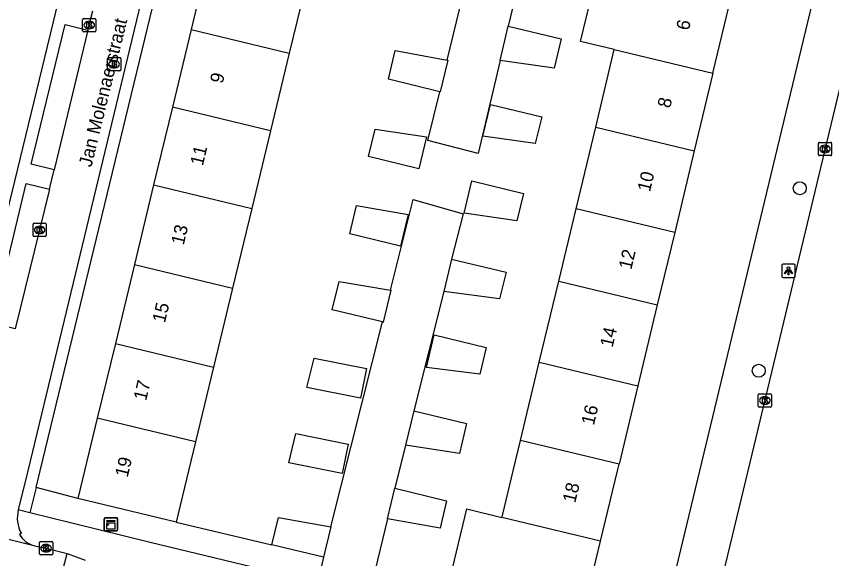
# Model space of a CAD drawing. Extents: x 162812 to 163818, y 381639 to 382470.
# Drawn here: x 163142.2 to 163203.7, y 382243.4 to 382284.3 of the extents above; entities that cross this region are included whole.
import ezdxf

# ---------------------------------------------------------------- set-up
doc = ezdxf.new("R2010")
doc.units = 0
for name, color, linetype in [('IMGEO_Boom', 7, 'Continuous'), ('IMGEO_Brandkraan', 7, 'Continuous'), ('IMGEO_Groenvoorziening', 7, 'Continuous'), ('IMGEO_Kast', 7, 'Continuous'), ('IMGEO_Kolk', 7, 'Continuous'), ('IMGEO_Lichtpunt', 7, 'Continuous'), ('IMGEO_Openbare_ruimte_label', 7, 'Continuous'), ('IMGEO_Pand', 7, 'Continuous'), ('IMGEO_Pand_nummerreeks', 7, 'Continuous'), ('IMGEO_Rijbaan_lokaal_open', 7, 'Continuous'), ('IMGEO_Voetpad_open', 7, 'Continuous')]:
    doc.layers.add(name, color=color, linetype=linetype)

msp = doc.modelspace()

# ---------------------------------------------------------------- linework, layer by layer
at = {"layer": 'IMGEO_Boom'}
for centre in [(163201.327, 382271.309), (163198.228, 382257.543)]:
    msp.add_circle(centre, 0.489, dxfattribs=at)
at = {"layer": 'IMGEO_Brandkraan'}
for p, q in [((163149.116, 382280.236), (163149.116, 382281.088)), ((163149.191, 382281.162), (163150.043, 382281.162)), ((163149.604, 382280.942), (163149.629, 382280.942)), ((163150.117, 382281.088), (163150.117, 382280.236)), ((163150.043, 382280.162), (163149.191, 382280.162)), ((163149.627, 382280.382), (163149.602, 382280.382))]:
    msp.add_line(p, q, dxfattribs=at)
for points in [[(163149.116, 382280.236), (163149.116, 382281.088)], [(163149.191, 382281.162), (163150.043, 382281.162)], [(163149.464, 382280.862), (163149.464, 382280.462), (163149.677, 382280.462)], [(163149.695, 382280.862), (163149.464, 382280.862)], [(163149.643, 382280.781), (163149.589, 382280.781), (163149.589, 382280.705)], [(163150.117, 382281.088), (163150.117, 382280.236)], [(163150.043, 382280.162), (163149.191, 382280.162)], [(163149.589, 382280.705), (163149.642, 382280.705)], [(163149.651, 382280.629), (163149.589, 382280.629), (163149.589, 382280.548)], [(163149.589, 382280.548), (163149.651, 382280.548)]]:
    msp.add_lwpolyline(points, dxfattribs=at)
for centre, radius, start, end in [((163149.193, 382281.086), 0.0765, 91.55205, 178.44795), ((163149.193, 382281.086), 0.0765, 91.55205, 178.44795), ((163149.644, 382280.743), 0.0379, 267.82845, 90.93552), ((163149.699, 382280.717), 0.145, 59.4692, 91.53667), ((163149.724, 382280.764), 0.0922, 285.51372, 58.15012), ((163150.041, 382281.086), 0.0765, 1.55205, 88.44795), ((163150.041, 382281.086), 0.0765, 1.55205, 88.44795), ((163149.193, 382280.238), 0.0765, 181.55205, 268.44795), ((163149.193, 382280.238), 0.0765, 181.55205, 268.44795), ((163149.652, 382280.588), 0.0404, 269.87594, 90.50774), ((163149.683, 382280.713), 0.251, 268.66757, 293.53466), ((163149.729, 382280.572), 0.105, 301.31148, 78.98903), ((163150.041, 382280.238), 0.0765, 271.55205, 358.44795), ((163150.041, 382280.238), 0.0765, 271.55205, 358.44795)]:
    msp.add_arc(centre, radius, start, end, dxfattribs=at)
for centre, major_axis, ratio, start_param, end_param in [((163149.603, 382280.662), (-0.387, 0.002), 0.722429, 4.712389, 7.853982), ((163149.628, 382280.662), (-0.39, 0.002), 0.717154, 1.570796, 4.712389)]:
    msp.add_ellipse(centre, major_axis=major_axis, ratio=ratio, start_param=start_param, end_param=end_param, dxfattribs=at)
at = {"layer": 'IMGEO_Groenvoorziening'}
for points in [[(163146.893, 382247.921), (163143.732, 382248.734)], [(163154.299, 382246.14), (163161.513, 382244.425)]]:
    msp.add_lwpolyline(points, dxfattribs=at)
at = {"layer": 'IMGEO_Kast'}
for p, q in [((163148.882, 382245.539), (163148.882, 382246.38)), ((163148.882, 382246.38), (163148.882, 382245.539)), ((163148.957, 382246.464), (163149.798, 382246.464)), ((163149.798, 382246.464), (163148.957, 382246.464)), ((163149.882, 382246.389), (163149.882, 382245.548)), ((163149.882, 382245.548), (163149.882, 382246.389)), ((163149.807, 382245.464), (163148.966, 382245.464)), ((163148.966, 382245.464), (163149.807, 382245.464))]:
    msp.add_line(p, q, dxfattribs=at)
for points in [[(163149.077, 382246.254), (163149.677, 382246.254), (163149.677, 382246.169), (163149.077, 382246.169), (163149.077, 382246.254)], [(163149.077, 382246.079), (163149.677, 382246.079), (163149.677, 382245.59), (163149.077, 382245.59), (163149.077, 382246.079)]]:
    msp.add_lwpolyline(points, dxfattribs=at)
msp.add_circle((163149.161, 382245.928), 0.0377, dxfattribs=at)
for centre, start, end in [((163148.96, 382246.386), 92.4484, 184.28452), ((163148.96, 382246.386), 92.4484, 184.28452), ((163149.804, 382246.386), 2.4484, 94.28452), ((163149.804, 382246.386), 2.4484, 94.28452), ((163148.96, 382245.542), 182.4484, 274.28452), ((163148.96, 382245.542), 182.4484, 274.28452), ((163149.804, 382245.542), 272.4484, 4.28452), ((163149.804, 382245.542), 272.4484, 4.28452)]:
    msp.add_arc(centre, 0.0779, start, end, dxfattribs=at)
at = {"layer": 'IMGEO_Kolk'}
for p, q in [((163147.25, 382283.191), (163147.25, 382284.043)), ((163147.325, 382284.117), (163148.177, 382284.117)), ((163147.738, 382283.897), (163147.763, 382283.897)), ((163148.251, 382284.043), (163148.251, 382283.191)), ((163147.761, 382283.337), (163147.736, 382283.337)), ((163148.177, 382283.117), (163147.325, 382283.117)), ((163202.728, 382273.845), (163202.728, 382274.697)), ((163202.803, 382274.771), (163203.655, 382274.771)), ((163203.729, 382274.697), (163203.729, 382273.845)), ((163203.239, 382273.991), (163203.214, 382273.991)), ((163203.216, 382274.551), (163203.241, 382274.551)), ((163203.655, 382273.771), (163202.803, 382273.771)), ((163143.506, 382267.741), (163143.506, 382268.593)), ((163143.581, 382268.667), (163144.433, 382268.667)), ((163143.994, 382268.447), (163144.019, 382268.447)), ((163144.507, 382268.593), (163144.507, 382267.741)), ((163144.017, 382267.887), (163143.992, 382267.887)), ((163144.433, 382267.667), (163143.581, 382267.667)), ((163198.192, 382254.879), (163198.192, 382255.731)), ((163198.267, 382255.805), (163199.119, 382255.805)), ((163198.68, 382255.585), (163198.705, 382255.585)), ((163199.193, 382255.731), (163199.193, 382254.879)), ((163198.703, 382255.025), (163198.678, 382255.025)), ((163199.119, 382254.805), (163198.267, 382254.805)), ((163143.995, 382243.737), (163143.995, 382244.589)), ((163144.07, 382244.663), (163144.922, 382244.663)), ((163144.996, 382244.589), (163144.996, 382243.737)), ((163144.506, 382243.883), (163144.481, 382243.883)), ((163144.483, 382244.443), (163144.508, 382244.443)), ((163144.922, 382243.663), (163144.07, 382243.663))]:
    msp.add_line(p, q, dxfattribs=at)
for points in [[(163147.25, 382283.191), (163147.25, 382284.043)], [(163147.325, 382284.117), (163148.177, 382284.117)], [(163147.571, 382283.817), (163147.694, 382283.817), (163147.694, 382283.666), (163147.824, 382283.817), (163147.988, 382283.817), (163147.842, 382283.666), (163147.995, 382283.417), (163147.843, 382283.417), (163147.758, 382283.581), (163147.694, 382283.514), (163147.694, 382283.417), (163147.571, 382283.417), (163147.571, 382283.817)], [(163148.251, 382284.043), (163148.251, 382283.191)], [(163148.177, 382283.117), (163147.325, 382283.117)], [(163202.728, 382273.845), (163202.728, 382274.697)], [(163202.803, 382274.771), (163203.655, 382274.771)], [(163203.729, 382274.697), (163203.729, 382273.845)], [(163203.049, 382274.471), (163203.172, 382274.471), (163203.172, 382274.32), (163203.302, 382274.471), (163203.466, 382274.471), (163203.32, 382274.32), (163203.473, 382274.071), (163203.321, 382274.071), (163203.236, 382274.235), (163203.172, 382274.168), (163203.172, 382274.071), (163203.049, 382274.071), (163203.049, 382274.471)], [(163203.655, 382273.771), (163202.803, 382273.771)], [(163143.506, 382267.741), (163143.506, 382268.593)], [(163143.581, 382268.667), (163144.433, 382268.667)], [(163144.507, 382268.593), (163144.507, 382267.741)], [(163143.827, 382268.367), (163143.95, 382268.367), (163143.95, 382268.216), (163144.08, 382268.367), (163144.244, 382268.367), (163144.098, 382268.216), (163144.251, 382267.967), (163144.099, 382267.967), (163144.014, 382268.131), (163143.95, 382268.064), (163143.95, 382267.967), (163143.827, 382267.967), (163143.827, 382268.367)], [(163144.433, 382267.667), (163143.581, 382267.667)], [(163198.192, 382254.879), (163198.192, 382255.731)], [(163198.267, 382255.805), (163199.119, 382255.805)], [(163199.193, 382255.731), (163199.193, 382254.879)], [(163198.513, 382255.505), (163198.636, 382255.505), (163198.636, 382255.354), (163198.766, 382255.505), (163198.93, 382255.505), (163198.784, 382255.354), (163198.937, 382255.105), (163198.785, 382255.105), (163198.7, 382255.269), (163198.636, 382255.202), (163198.636, 382255.105), (163198.513, 382255.105), (163198.513, 382255.505)], [(163199.119, 382254.805), (163198.267, 382254.805)], [(163143.995, 382243.737), (163143.995, 382244.589)], [(163144.07, 382244.663), (163144.922, 382244.663)], [(163144.996, 382244.589), (163144.996, 382243.737)], [(163144.316, 382244.363), (163144.439, 382244.363), (163144.439, 382244.212), (163144.569, 382244.363), (163144.733, 382244.363), (163144.587, 382244.212), (163144.74, 382243.963), (163144.588, 382243.963), (163144.503, 382244.127), (163144.439, 382244.06), (163144.439, 382243.963), (163144.316, 382243.963), (163144.316, 382244.363)], [(163144.922, 382243.663), (163144.07, 382243.663)]]:
    msp.add_lwpolyline(points, dxfattribs=at)
for centre, start, end in [((163147.327, 382284.041), 91.55205, 178.44795), ((163147.327, 382284.041), 91.55205, 178.44795), ((163148.175, 382284.041), 1.55205, 88.44795), ((163148.175, 382284.041), 1.55205, 88.44795), ((163147.327, 382283.193), 181.55205, 268.44795), ((163147.327, 382283.193), 181.55205, 268.44795), ((163148.175, 382283.193), 271.55205, 358.44795), ((163148.175, 382283.193), 271.55205, 358.44795), ((163202.805, 382274.695), 91.55205, 178.44795), ((163202.805, 382274.695), 91.55205, 178.44795), ((163203.653, 382274.695), 1.55205, 88.44795), ((163203.653, 382274.695), 1.55205, 88.44795), ((163202.805, 382273.847), 181.55205, 268.44795), ((163202.805, 382273.847), 181.55205, 268.44795), ((163203.653, 382273.847), 271.55205, 358.44795), ((163203.653, 382273.847), 271.55205, 358.44795), ((163143.583, 382268.591), 91.55205, 178.44795), ((163143.583, 382268.591), 91.55205, 178.44795), ((163144.431, 382268.591), 1.55205, 88.44795), ((163144.431, 382268.591), 1.55205, 88.44795), ((163143.583, 382267.743), 181.55205, 268.44795), ((163143.583, 382267.743), 181.55205, 268.44795), ((163144.431, 382267.743), 271.55205, 358.44795), ((163144.431, 382267.743), 271.55205, 358.44795), ((163198.269, 382255.729), 91.55205, 178.44795), ((163198.269, 382255.729), 91.55205, 178.44795), ((163199.117, 382255.729), 1.55205, 88.44795), ((163199.117, 382255.729), 1.55205, 88.44795), ((163198.269, 382254.881), 181.55205, 268.44795), ((163198.269, 382254.881), 181.55205, 268.44795), ((163199.117, 382254.881), 271.55205, 358.44795), ((163199.117, 382254.881), 271.55205, 358.44795), ((163144.072, 382244.587), 91.55205, 178.44795), ((163144.072, 382244.587), 91.55205, 178.44795), ((163144.92, 382244.587), 1.55205, 88.44795), ((163144.92, 382244.587), 1.55205, 88.44795), ((163144.072, 382243.739), 181.55205, 268.44795), ((163144.072, 382243.739), 181.55205, 268.44795), ((163144.92, 382243.739), 271.55205, 358.44795), ((163144.92, 382243.739), 271.55205, 358.44795)]:
    msp.add_arc(centre, 0.0765, start, end, dxfattribs=at)
for centre, major_axis, ratio, start_param, end_param in [((163147.737, 382283.617), (-0.387, 0.002), 0.722429, 4.712389, 7.853982), ((163147.762, 382283.617), (-0.39, 0.002), 0.717154, 1.570796, 4.712389), ((163203.215, 382274.271), (-0.387, 0.002), 0.722429, 4.712389, 7.853982), ((163203.24, 382274.271), (-0.39, 0.002), 0.717154, 1.570796, 4.712389), ((163143.993, 382268.167), (-0.387, 0.002), 0.722429, 4.712389, 7.853982), ((163144.018, 382268.167), (-0.39, 0.002), 0.717154, 1.570796, 4.712389), ((163198.679, 382255.305), (-0.387, 0.002), 0.722429, 4.712389, 7.853982), ((163198.704, 382255.305), (-0.39, 0.002), 0.717154, 1.570796, 4.712389), ((163144.482, 382244.163), (-0.387, 0.002), 0.722429, 4.712389, 7.853982), ((163144.507, 382244.163), (-0.39, 0.002), 0.717154, 1.570796, 4.712389)]:
    msp.add_ellipse(centre, major_axis=major_axis, ratio=ratio, start_param=start_param, end_param=end_param, dxfattribs=at)
at = {"layer": 'IMGEO_Lichtpunt'}
for p, q in [((163199.977, 382265.49), (163199.977, 382264.683)), ((163199.977, 382265.49), (163199.977, 382264.683)), ((163200.879, 382265.585), (163200.071, 382265.585)), ((163200.879, 382265.585), (163200.071, 382265.585)), ((163200.973, 382264.683), (163200.973, 382265.49)), ((163200.973, 382264.683), (163200.973, 382265.49)), ((163200.071, 382264.589), (163200.879, 382264.589)), ((163200.071, 382264.589), (163200.879, 382264.589))]:
    msp.add_line(p, q, dxfattribs=at)
for points in [[(163200.351, 382265.154), (163200.39, 382265.126), (163200.202, 382264.864), (163200.164, 382264.891), (163200.351, 382265.154)], [(163200.453, 382265.106), (163200.5, 382265.106), (163200.5, 382264.784), (163200.453, 382264.784), (163200.453, 382265.106)], [(163200.563, 382265.126), (163200.601, 382265.153), (163200.788, 382264.891), (163200.749, 382264.863), (163200.563, 382265.126)]]:
    msp.add_lwpolyline(points, dxfattribs=at)
msp.add_circle((163200.476, 382265.288), 0.0994, dxfattribs=at)
for centre, start, end in [((163200.071, 382265.49), 90, 180), ((163200.071, 382265.49), 90, 180), ((163200.879, 382265.49), 0, 90), ((163200.879, 382265.49), 0, 90), ((163200.071, 382264.683), 180, 270), ((163200.071, 382264.683), 180, 270), ((163200.879, 382264.683), 270, 0), ((163200.879, 382264.683), 270, 360)]:
    msp.add_arc(centre, 0.0946, start, end, dxfattribs=at)
at = {"layer": 'IMGEO_Pand'}
for points in [[(163156.897, 382289.378), (163155.425, 382283.276)], [(163164.298, 382287.592), (163162.826, 382281.49)], [(163187.342, 382281.768), (163184.792, 382282.38), (163185.667, 382286.022), (163184.226, 382286.263)], [(163194.78, 382279.981), (163196.163, 382285.737)], [(163155.425, 382283.276), (163154.012, 382277.422)], [(163155.425, 382283.276), (163162.826, 382281.49)], [(163179.346, 382283.527), (163183.334, 382282.569), (163182.804, 382280.361), (163178.727, 382280.951)], [(163178.727, 382280.951), (163179.346, 382283.527)], [(163162.826, 382281.49), (163161.414, 382275.636)], [(163174.173, 382278.593), (163170.3, 382279.527), (163170.823, 382281.695), (163174.748, 382280.968)], [(163185.936, 382275.914), (163187.342, 382281.768)], [(163187.342, 382281.768), (163194.78, 382279.981)], [(163174.748, 382280.968), (163174.783, 382280.961), (163174.209, 382278.584), (163174.173, 382278.593)], [(163194.78, 382279.981), (163193.373, 382274.127)], [(163154.012, 382277.422), (163152.6, 382271.569)], [(163161.414, 382275.636), (163154.012, 382277.422)], [(163181.864, 382276.7), (163181.378, 382274.677), (163177.421, 382275.231), (163177.997, 382277.628), (163181.864, 382276.7)], [(163184.458, 382269.759), (163185.936, 382275.914)], [(163185.936, 382275.914), (163193.373, 382274.127)], [(163161.414, 382275.636), (163160.002, 382269.784)], [(163173.175, 382275.198), (163172.593, 382272.787), (163168.808, 382273.701), (163169.308, 382275.774), (163173.175, 382275.198)], [(163193.373, 382274.127), (163191.894, 382267.972)], [(163152.6, 382271.569), (163151.151, 382265.563)], [(163152.6, 382271.569), (163160.002, 382269.784)], [(163180.482, 382270.925), (163179.987, 382268.865), (163176.013, 382269.442), (163176.593, 382271.859), (163180.482, 382270.925)], [(163160.002, 382269.784), (163158.553, 382263.777)], [(163171.226, 382266.947), (163167.386, 382267.874), (163167.9, 382270.006), (163171.799, 382269.322), (163171.226, 382266.947)], [(163183.148, 382264.303), (163184.458, 382269.759)], [(163191.894, 382267.972), (163184.458, 382269.759)], [(163191.894, 382267.972), (163190.583, 382262.516)], [(163151.151, 382265.563), (163149.715, 382259.613)], [(163151.151, 382265.563), (163158.553, 382263.777)], [(163175.063, 382265.964), (163179.178, 382264.975), (163178.693, 382262.959), (163174.478, 382263.53)], [(163175.063, 382265.964), (163174.478, 382263.53)], [(163169.853, 382261.227), (163166.072, 382262.139), (163166.589, 382264.283), (163170.455, 382263.623)], [(163181.682, 382258.2), (163183.148, 382264.303)], [(163183.148, 382264.303), (163190.583, 382262.516)], [(163158.553, 382263.777), (163157.118, 382257.827)], [(163169.853, 382261.227), (163169.935, 382261.207), (163170.515, 382263.613), (163170.455, 382263.623)], [(163190.583, 382262.516), (163189.117, 382256.414)], [(163177.675, 382259.313), (163177.189, 382257.288), (163173.168, 382257.803), (163173.756, 382260.254), (163177.675, 382259.313)], [(163149.715, 382259.613), (163148.351, 382253.961)], [(163149.715, 382259.613), (163157.118, 382257.827)], [(163168.194, 382255.48), (163164.161, 382256.291), (163164.697, 382258.499), (163168.641, 382257.705), (163168.194, 382255.48)], [(163180.265, 382252.298), (163181.682, 382258.2)], [(163181.682, 382258.2), (163189.117, 382256.414)], [(163157.118, 382257.827), (163155.755, 382252.175)], [(163189.117, 382256.414), (163187.699, 382250.511)], [(163172.221, 382254.514), (163176.201, 382253.558), (163175.661, 382251.306), (163171.602, 382251.937)], [(163172.221, 382254.514), (163171.602, 382251.937)], [(163148.351, 382253.961), (163147.395, 382250), (163146.893, 382247.921)], [(163155.755, 382252.175), (163148.351, 382253.961)], [(163166.831, 382249.792), (163162.798, 382250.603), (163163.334, 382252.81), (163167.278, 382252.017), (163166.831, 382249.792)], [(163155.755, 382252.175), (163155.23, 382250), (163154.299, 382246.14)], [(163178.87, 382246.492), (163178.927, 382246.728), (163179.713, 382250), (163180.265, 382252.298)], [(163187.699, 382250.511), (163180.265, 382252.298)], [(163186.304, 382244.706), (163187.576, 382250), (163187.699, 382250.511)], [(163170.788, 382248.691), (163174.697, 382247.748), (163174.199, 382245.683), (163170.232, 382246.387)], [(163170.232, 382246.387), (163170.788, 382248.691)], [(163154.299, 382246.14), (163146.893, 382247.921)], [(163174.805, 382241.277), (163176.211, 382247.131), (163178.87, 382246.492)], [(163161.513, 382244.425), (163162.007, 382246.47), (163165.967, 382245.764)], [(163186.304, 382244.706), (163178.87, 382246.492)], [(163165.967, 382245.764), (163165.416, 382243.483)], [(163184.898, 382238.854), (163186.304, 382244.706)], [(163165.416, 382243.483), (163161.513, 382244.425)]]:
    msp.add_lwpolyline(points, dxfattribs=at)
at = {"layer": 'IMGEO_Rijbaan_lokaal_open'}
for points in [[(163157.45, 382309.459), (163143.104, 382250), (163142.397, 382247.069)], [(163147.649, 382283.226), (163148.02, 382284.701)], [(163147.649, 382283.226), (163145.094, 382272.703)], [(163190.618, 382221.745), (163197.427, 382250), (163205.323, 382282.906)], [(163144.748, 382271.241), (163145.094, 382272.703)], [(163144.748, 382271.241), (163144.006, 382268.167), (163142.171, 382260.712)], [(163136.694, 382246.075), (163143.569, 382244.359)], [(163142.625, 382245.269), (163142.487, 382245.21)], [(163143.569, 382244.359), (163143.654, 382244.338), (163143.74, 382244.321), (163144.497, 382244.161), (163146.086, 382243.768)], [(163145.726, 382242.413), (163146.086, 382243.768)]]:
    msp.add_lwpolyline(points, dxfattribs=at)
for centre, radius, start, end in [((163144.808, 382246.46), 2.486, 165.81884, 208.6192), ((163144.039, 382246.069), 1.774, 208.98292, 254.64653)]:
    msp.add_arc(centre, radius, start, end, dxfattribs=at)
at = {"layer": 'IMGEO_Voetpad_open'}
for points in [[(163135.523, 382248.664), (163136.536, 382250), (163136.747, 382250.336), (163137.011, 382250.814), (163151.17, 382309.066), (163147.739, 382309.906)], [(163143.732, 382248.734), (163144.039, 382250), (163157.996, 382307.58), (163161.374, 382306.761), (163161.303, 382306.543)], [(163174.748, 382280.968), (163179.856, 382302.069), (163168.453, 382304.819)], [(163190.746, 382237.354), (163193.788, 382250), (163204.875, 382296.09), (163198.99, 382297.502)], [(163181.603, 382292.88), (163179.346, 382283.527)], [(163145.094, 382272.703), (163143.364, 382273.124), (163145.921, 382283.659), (163147.649, 382283.226)], [(163178.727, 382280.951), (163177.079, 382273.933), (163173.283, 382274.916), (163174.173, 382278.593)], [(163142.171, 382260.712), (163140.456, 382261.14), (163142.996, 382271.662), (163144.748, 382271.241)], [(163170.455, 382263.623), (163172.175, 382270.465), (163175.938, 382269.391), (163175.063, 382265.964)], [(163174.478, 382263.53), (163172.221, 382254.514)], [(163165.967, 382245.764), (163169.853, 382261.227)], [(163171.602, 382251.937), (163170.788, 382248.691)], [(163143.732, 382248.734), (163143.272, 382246.834)], [(163143.272, 382246.834), (163142.397, 382247.069)], [(163164.968, 382241.557), (163152.35, 382244.592), (163146.526, 382246.03), (163143.272, 382246.834)], [(163170.232, 382246.387), (163169.303, 382242.529)], [(163146.086, 382243.768), (163147.445, 382243.263)], [(163165.416, 382243.483), (163164.968, 382241.557)]]:
    msp.add_lwpolyline(points, dxfattribs=at)

# ---------------------------------------------------------------- texts
at = {"layer": 'IMGEO_Openbare_ruimte_label'}
msp.add_text('Jan Molenaerstraat', height=1, rotation=76.29711, dxfattribs=at).set_placement((163147.906, 382272.859))
at = {"layer": 'IMGEO_Pand_nummerreeks'}
for s, rotation, p in [('6', 76.48987, (163192.952, 382283.161)), ('9', 76.4329, (163157.805, 382279.159)), ('8', 76.48904, (163191.544, 382277.3)), ('11', 76.4329, (163156.309, 382272.955)), ('10', 76.48904, (163190.027, 382270.987)), ('13', 76.4329, (163154.865, 382266.975)), ('12', 76.48904, (163188.617, 382265.116)), ('15', 76.4329, (163153.449, 382261.107)), ('14', 76.48904, (163187.207, 382259.254)), ('17', 76.4329, (163152.033, 382255.239)), ('16', 76.48904, (163185.798, 382253.39)), ('19', 76.42895, (163150.639, 382249.458)), ('18', 76.48987, (163184.39, 382247.528))]:
    msp.add_text(s, height=1, rotation=rotation, dxfattribs=at).set_placement(p)

doc.saveas('drawing.dxf')
